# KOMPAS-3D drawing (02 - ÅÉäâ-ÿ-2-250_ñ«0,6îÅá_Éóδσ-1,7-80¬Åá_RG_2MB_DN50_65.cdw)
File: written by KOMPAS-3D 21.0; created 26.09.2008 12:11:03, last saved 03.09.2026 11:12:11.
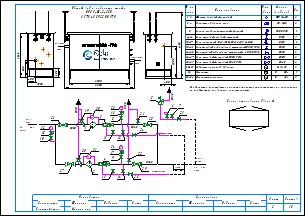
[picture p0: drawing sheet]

Sheets 1-2: A3, landscape

Document properties: Наименование: Макро:21; Автор: RaskoAdmin; Форматы листов документа: 2xA3; Полное имя файла: \\UR38nt01\Departments\КТО\КБ ПУРДГ\Заявки\Прайс-лист на типовые шкафы ГРПШ\ПРДГ_стандарт_20_03_2026\ПРДГ с RG_2MB\ПРДГ-Ш-2-250_до0,6МПа_Рвых-1,7-80кПа_RG_2MB_DN50_65.cdw

Title block, sheet 1: Наименование: Пункт учета газа / ПУГ-Ш-400-Р / ЛГТИ.485922.001ТУ; designation: ЛГТИ.03.4411141; sheet number: 1; Количество листов документа: 2; organisation: ООО "ЭЛЬСТЕР Газэлектроника"; Форматы листов документа: A3; stored path: C:\Рабочие документы\Компас\ПУГ\Схема.cdw; Разработал: Устинов; Проверил: Кошкин; Утвердил: Кошкин
Title block, sheet 2: sheet number: 2; stored path: D:\Рабочие документы\Заявки\ПУРДГ\ПУРДГ-ШУЭО-2-100-Р 4411220.cdw; designation, second copy: ЛГТИ.03.4411141-

Views: Вид 1, Вид 2
Referenced files: wcvoit.frw
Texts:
  Normal
  Вход
  газа
  PDI
  Выход
  Р=     кПа
  DN65
  DN50
  DN20
  Импульс DN20
  ≥5DN
  HYSWLongFangSong
  № на
  схеме
  Усл.
  обозн.
  Марка
  (модель)
  Кол.
  Фильтр газовый фланцевый
  ФГ 16-50
  Регулятор давления газа
  RG/2MB
  Клапан предохранительный сбросной
  КПС DN20
  Кран шаровой газовый латунный
  DN15
  Кран кнопочный VE-РАСКО-НЗ-1,6-G1/2-М20
  Кран шаровой "под приварку" штуцерный DN20 PN16
  Кран шаровой "под приварку" штуцерный п/п DN20 PN16
  Кран шаровой фланцевый DN50 PN16
  Кран шаровой фланцевый DN65 PN16
  Индикатор перепада давления
  Delta 15
  Манометр
  Манометр-напоромер
  0...     МПа
  0...     кПа
  Общий вид и габариты шкафа
  ПРДГ-Ш-2-250
  Выход газа
  Вход газа
  Схема открывания дверей
  Р=        МПа
  logo-rasko-ge.png
  Предприятие изготовитель может заменять комплектующие на аналогичные,
  не ухудшающие заявленных характеристик.
  Должность
  Конструктор
  Фамилия
  Подпись
  Дата
  Согласовано
  Максимкин
  Лист
  Листов
  POLYLINE_STYLE_0.18_RGB_0_0_0
  POLYLINE_STYLE_0.50_RGB_0_0_0
  POLYLINE_STYLE_0.34_RGB_0_0_0
  PHANTOM_RGB_0_0_0_SC_1_THICK_0.18
  K5LT_THIN_RGB_0_0_0_THICK_0.18
  K5LT32769_RGB_0_0_0_THICK_0.18
  K5LT12_RGB_0_0_0_SC_1_THICK_0.18
  K5LT_DASHED_RGB_0_0_0_SC_1_THICK_0.18
  ACISOTGL_RGB_0_0_0_SC_0.8_THICK_0.25
  CONTINUOUS_RGB_0_127_31_THICK_0.3
  CONTINUOUS_RGB_0_0_255_THICK_0.35
  CONTINUOUS_RGB_255_0_0_THICK_0.35
  POLYLINE_STYLE_0.25_RGB_0_0_0
  CONTINUOUS_RGB_0_0_0_THICK_0.5
  POLYLINE_STYLE_0.35_RGB_0_0_255
  CONTINUOUS_RGB_0_0_0_THICK_0.4
  CONTINUOUS_RGB_0_0_0_THICK_0.35
  Без оформления
Dimensions and other numbers on the sheet: 1; 2; 3; 4; 5; 10; 27; 28; 29; 23; 8; 12; 19; 20; 21; 22; 25; 24; 30; 31; 15; 16; 26; 6; 7; 11; 14; 13; 33; 1, 2; 3, 4; 6-14; 9; 15-17; 18-23; 24-25; 26-27; 28-29; 30-31; 32; 33-34; 400; 1050; 500; 305; 2300; 1565; 2600; 17; 34; 1000; 4130; 18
